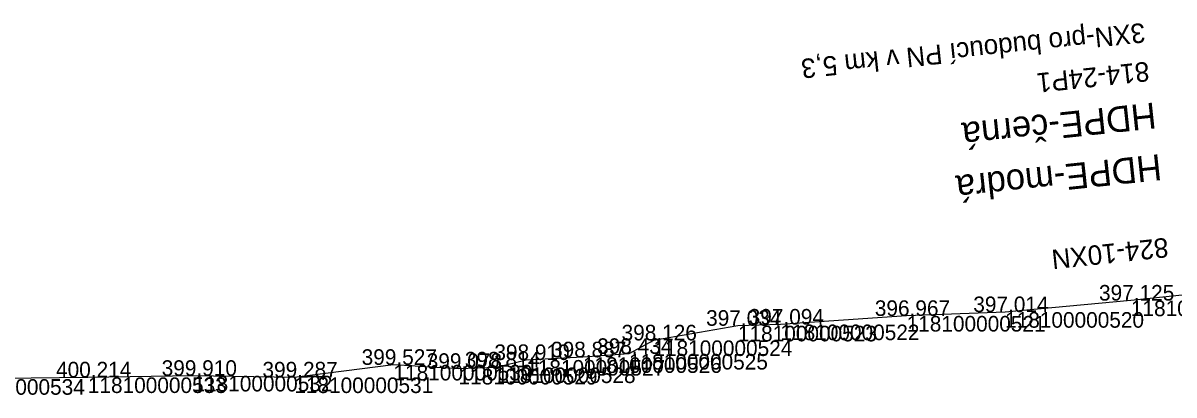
# Model space of a CAD drawing. Extents: x -727171 to -722443, y -945718 to -941834.
# Drawn here: x -723489.4 to -723400.7, y -945345 to -945316.4 of the extents above; entities that cross this region are included whole.
import ezdxf

# ---------------------------------------------------------------- set-up
doc = ezdxf.new("R2010")
doc.units = 0
for name, color, linetype in [('Vrstva 28', 7, 'Continuous'), ('Vrstva 31', 7, 'Continuous'), ('Vrstva 33', 7, 'Continuous'), ('Vrstva 60', 7, 'Continuous'), ('Vrstva 61', 7, 'Continuous')]:
    doc.layers.add(name, color=color, linetype=linetype)

msp = doc.modelspace()

# ---------------------------------------------------------------- linework, layer by layer
at = {"layer": 'Vrstva 28'}
msp.add_lwpolyline([(-723398.387, -945337.169), (-723404.052, -945337.768), (-723413.747, -945338.657), (-723421.336, -945338.952), (-723431.058, -945339.616), (-723434.339, -945339.708), (-723440.854, -945340.836), (-723442.738, -945341.876), (-723446.292, -945342.137), (-723450.659, -945342.345), (-723452.936, -945342.917), (-723455.872, -945343.028), (-723460.889, -945342.718), (-723468.534, -945343.687), (-723476.304, -945343.564), (-723484.446, -945343.684), (-723495.39, -945343.818)], dxfattribs=at)
at = {"layer": 'Vrstva 31'}
msp.add_lwpolyline([(-723398.387, -945337.169), (-723404.052, -945337.768), (-723413.747, -945338.657), (-723421.336, -945338.952), (-723431.058, -945339.616), (-723434.339, -945339.708), (-723440.854, -945340.836), (-723442.738, -945341.876), (-723446.292, -945342.137), (-723450.659, -945342.345), (-723452.936, -945342.917), (-723455.872, -945343.028), (-723460.889, -945342.718), (-723468.534, -945343.687), (-723476.304, -945343.564), (-723484.446, -945343.684), (-723495.39, -945343.818)], dxfattribs=at)
at = {"layer": 'Vrstva 33'}
msp.add_lwpolyline([(-723398.387, -945337.169), (-723404.052, -945337.768), (-723413.747, -945338.657), (-723421.336, -945338.952), (-723431.058, -945339.616), (-723434.339, -945339.708), (-723440.854, -945340.836), (-723442.738, -945341.876), (-723446.292, -945342.137), (-723450.659, -945342.345), (-723452.936, -945342.917), (-723455.872, -945343.028), (-723460.889, -945342.718), (-723468.534, -945343.687), (-723476.304, -945343.564), (-723484.446, -945343.684), (-723495.39, -945343.818)], dxfattribs=at)
at = {"layer": 'Vrstva 60'}
for p, q in [((-723404.052, -945337.768), (-723404.052, -945337.768)), ((-723421.336, -945338.952), (-723421.336, -945338.952)), ((-723413.747, -945338.657), (-723413.747, -945338.657)), ((-723434.339, -945339.708), (-723434.339, -945339.708)), ((-723431.058, -945339.616), (-723431.058, -945339.616)), ((-723440.854, -945340.836), (-723440.854, -945340.836)), ((-723450.659, -945342.345), (-723450.659, -945342.345)), ((-723446.292, -945342.137), (-723446.292, -945342.137)), ((-723442.738, -945341.876), (-723442.738, -945341.876)), ((-723460.889, -945342.718), (-723460.889, -945342.718)), ((-723455.872, -945343.028), (-723455.872, -945343.028)), ((-723452.936, -945342.917), (-723452.936, -945342.917)), ((-723484.446, -945343.684), (-723484.446, -945343.684)), ((-723476.304, -945343.564), (-723476.304, -945343.564)), ((-723468.534, -945343.687), (-723468.534, -945343.687))]:
    msp.add_line(p, q, dxfattribs=at)

# ---------------------------------------------------------------- texts
at = {"layer": 'Vrstva 28'}
for s, p in [('3XN-pro budoucí PN v km 5,3', (-723403.03, -945316.385)), ('814-24P1', (-723402.714, -945319.368))]:
    msp.add_text(s, height=1.5, rotation=186.03586, dxfattribs=at).set_placement(p)
at = {"layer": 'Vrstva 31'}
msp.add_text('824-10XN', height=1.5, rotation=186.03586, dxfattribs=at).set_placement((-723401.246, -945332.921))
at = {"layer": 'Vrstva 33'}
for s, p in [('HDPE-černá', (-723402.224, -945322.509)), ('HDPE-modrá', (-723401.803, -945326.487))]:
    msp.add_text(s, height=2, rotation=186.03586, dxfattribs=at).set_placement(p)
at = {"layer": 'Vrstva 60'}
for s, p in [('118100000519', (-723404.052, -945338.968)), ('118100000521', (-723421.336, -945340.152)), ('118100000520', (-723413.747, -945339.857)), ('118100000523', (-723434.339, -945340.908)), ('118100000522', (-723431.058, -945340.816)), ('118100000524', (-723440.854, -945342.036)), ('118100000527', (-723450.659, -945343.545)), ('118100000526', (-723446.292, -945343.337)), ('118100000525', (-723442.738, -945343.076)), ('118100000530', (-723460.889, -945343.918)), ('118100000529', (-723455.872, -945344.228)), ('118100000528', (-723452.936, -945344.117)), ('118100000534', (-723495.39, -945345.018)), ('118100000533', (-723484.446, -945344.884)), ('118100000532', (-723476.304, -945344.764)), ('118100000531', (-723468.534, -945344.887))]:
    msp.add_text(s, height=1.2, dxfattribs=at).set_placement(p)
at = {"layer": 'Vrstva 61'}
for s, p in [('397.125', (-723406.508, -945337.768)), ('396.967', (-723423.788, -945338.952)), ('397.014', (-723416.198, -945338.657)), ('397.034', (-723436.79, -945339.708)), ('397.094', (-723433.509, -945339.616)), ('398.126', (-723443.306, -945340.836)), ('398.434', (-723445.189, -945341.876)), ('399.527', (-723463.341, -945342.718)), ('398.910', (-723453.11, -945342.345)), ('398.887', (-723448.744, -945342.137)), ('400.214', (-723486.897, -945343.684)), ('399.910', (-723478.755, -945343.564)), ('399.287', (-723470.986, -945343.687)), ('399.078', (-723458.326, -945343.028)), ('398.814', (-723455.387, -945342.917))]:
    msp.add_text(s, height=1.2, dxfattribs=at).set_placement(p)

doc.saveas('drawing.dxf')
